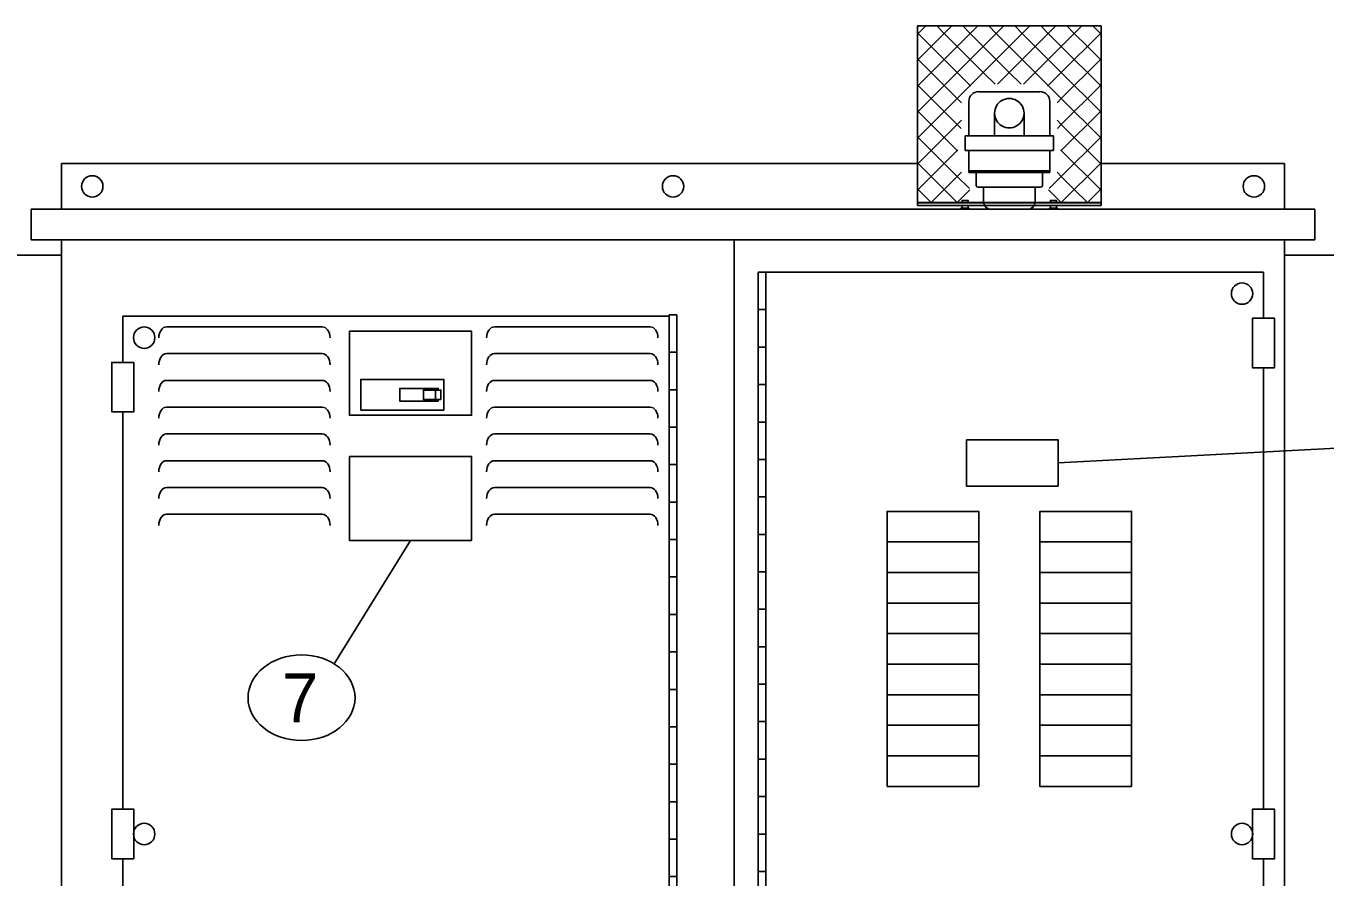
# Model space of a CAD drawing. Extents: x 99862 to 103680, y 99470 to 105076.
# Drawn here: x 100953.3 to 101378.5, y 100952 to 101230.5 of the extents above; entities that cross this region are included whole.
import ezdxf

# ---------------------------------------------------------------- set-up
doc = ezdxf.new("R2010")
doc.units = 0
for name, color, linetype in [('Level 1', 7, 'Continuous'), ('Level 11', 7, 'Continuous'), ('Level 15', 7, 'Continuous'), ('Level 20', 7, 'Continuous'), ('Level 34', 7, 'Continuous'), ('Level 40', 7, 'Continuous')]:
    doc.layers.add(name, color=color, linetype=linetype)

msp = doc.modelspace()

# ---------------------------------------------------------------- linework, layer by layer
at = {"layer": 'Level 1'}
for p, q in [((101244.91, 101172.75), (101244.91, 101230.51)), ((101304.91, 101230.51), (101244.91, 101230.51)), ((101244.91, 101228.28), (101245.13, 101228.06)), ((101245.13, 101228.06), (101247.58, 101230.51)), ((101251.19, 101230.51), (101253.64, 101228.06)), ((101256.09, 101230.51), (101253.64, 101228.06)), ((101262.15, 101228.06), (101259.7, 101230.51)), ((101264.6, 101230.51), (101262.15, 101228.06)), ((101270.66, 101228.06), (101268.2, 101230.51)), ((101273.11, 101230.51), (101270.66, 101228.06)), ((101279.16, 101228.06), (101276.71, 101230.51)), ((101281.62, 101230.51), (101279.16, 101228.06)), ((101287.67, 101228.06), (101285.22, 101230.51)), ((101290.12, 101230.51), (101287.67, 101228.06)), ((101293.73, 101230.51), (101296.18, 101228.06)), ((101296.18, 101228.06), (101298.63, 101230.51)), ((101304.69, 101228.06), (101302.24, 101230.51)), ((101304.91, 101228.28), (101304.69, 101228.06)), ((101304.91, 101172.75), (101304.91, 101230.51)), ((101245.13, 101228.06), (101244.91, 101227.84)), ((101249.38, 101223.8), (101245.13, 101228.06)), ((101253.64, 101228.06), (101249.38, 101223.8)), ((101253.64, 101228.06), (101257.89, 101223.8)), ((101257.89, 101223.8), (101262.15, 101228.06)), ((101262.15, 101228.06), (101266.4, 101223.8)), ((101266.4, 101223.8), (101270.66, 101228.06)), ((101270.66, 101228.06), (101274.91, 101223.8)), ((101274.91, 101223.8), (101279.16, 101228.06)), ((101279.16, 101228.06), (101283.42, 101223.8)), ((101283.42, 101223.8), (101287.67, 101228.06)), ((101287.67, 101228.06), (101291.93, 101223.8)), ((101291.93, 101223.8), (101296.18, 101228.06)), ((101296.18, 101228.06), (101300.44, 101223.8)), ((101300.44, 101223.8), (101304.69, 101228.06)), ((101304.69, 101228.06), (101304.91, 101227.84)), ((101244.91, 101219.77), (101245.13, 101219.55)), ((101245.13, 101219.55), (101249.38, 101223.8)), ((101249.38, 101223.8), (101253.64, 101219.55)), ((101257.89, 101223.8), (101253.64, 101219.55)), ((101262.15, 101219.55), (101257.89, 101223.8)), ((101266.4, 101223.8), (101262.15, 101219.55)), ((101270.66, 101219.55), (101266.4, 101223.8)), ((101274.91, 101223.8), (101270.66, 101219.55)), ((101279.16, 101219.55), (101274.91, 101223.8)), ((101283.42, 101223.8), (101279.16, 101219.55)), ((101287.67, 101219.55), (101283.42, 101223.8)), ((101291.93, 101223.8), (101287.67, 101219.55)), ((101296.18, 101219.55), (101291.93, 101223.8)), ((101300.44, 101223.8), (101296.18, 101219.55)), ((101304.69, 101219.55), (101300.44, 101223.8)), ((101304.91, 101219.77), (101304.69, 101219.55)), ((101245.13, 101219.55), (101244.91, 101219.33)), ((101249.38, 101215.3), (101245.13, 101219.55)), ((101253.64, 101219.55), (101249.38, 101215.3)), ((101253.64, 101219.55), (101257.89, 101215.3)), ((101257.89, 101215.3), (101262.15, 101219.55)), ((101262.15, 101219.55), (101266.4, 101215.3)), ((101266.4, 101215.3), (101270.66, 101219.55)), ((101270.66, 101219.55), (101274.91, 101215.3)), ((101274.91, 101215.3), (101279.16, 101219.55)), ((101279.16, 101219.55), (101283.42, 101215.3)), ((101283.42, 101215.3), (101287.67, 101219.55)), ((101287.67, 101219.55), (101291.93, 101215.3)), ((101291.93, 101215.3), (101296.18, 101219.55)), ((101296.18, 101219.55), (101300.44, 101215.3)), ((101300.44, 101215.3), (101304.69, 101219.55)), ((101304.69, 101219.55), (101304.91, 101219.33)), ((101244.91, 101211.26), (101245.13, 101211.04)), ((101245.13, 101211.04), (101249.38, 101215.3)), ((101249.38, 101215.3), (101253.64, 101211.04)), ((101257.89, 101215.3), (101253.64, 101211.04)), ((101262.15, 101211.04), (101257.89, 101215.3)), ((101266.4, 101215.3), (101262.15, 101211.04)), ((101270.28, 101211.42), (101266.4, 101215.3)), ((101274.91, 101215.3), (101271.04, 101211.42)), ((101278.78, 101211.42), (101274.91, 101215.3)), ((101283.42, 101215.3), (101279.54, 101211.42)), ((101287.67, 101211.04), (101283.42, 101215.3)), ((101291.93, 101215.3), (101287.67, 101211.04)), ((101296.18, 101211.04), (101291.93, 101215.3)), ((101300.44, 101215.3), (101296.18, 101211.04)), ((101304.69, 101211.04), (101300.44, 101215.3)), ((101304.91, 101211.26), (101304.69, 101211.04)), ((101245.13, 101211.04), (101244.91, 101210.82)), ((101249.38, 101206.79), (101245.13, 101211.04)), ((101253.64, 101211.04), (101249.38, 101206.79)), ((101253.64, 101211.04), (101257.89, 101206.79)), ((101257.89, 101206.79), (101262.15, 101211.04)), ((101262.15, 101211.04), (101262.36, 101210.83)), ((101284.94, 101209.01), (101264.88, 101209.01)), ((101287.46, 101210.82), (101287.67, 101211.04)), ((101287.67, 101211.04), (101291.93, 101206.79)), ((101291.93, 101206.79), (101296.18, 101211.04)), ((101296.18, 101211.04), (101300.44, 101206.79)), ((101300.44, 101206.79), (101304.69, 101211.04)), ((101304.69, 101211.04), (101304.91, 101210.82)), ((101244.91, 101202.75), (101245.13, 101202.53)), ((101245.13, 101202.53), (101249.38, 101206.79)), ((101249.38, 101206.79), (101253.64, 101202.53)), ((101257.89, 101206.79), (101253.64, 101202.53)), ((101259.27, 101205.41), (101257.89, 101206.79)), ((101261.67, 101194.58), (101261.67, 101205.81)), ((101288.15, 101194.58), (101288.15, 101205.81)), ((101291.93, 101206.79), (101290.55, 101205.41)), ((101296.18, 101202.53), (101291.93, 101206.79)), ((101300.44, 101206.79), (101296.18, 101202.53)), ((101304.69, 101202.53), (101300.44, 101206.79)), ((101304.91, 101202.75), (101304.69, 101202.53)), ((101245.13, 101202.53), (101244.91, 101202.31)), ((101249.38, 101198.28), (101245.13, 101202.53)), ((101253.64, 101202.53), (101249.38, 101198.28)), ((101253.64, 101202.53), (101257.89, 101198.28)), ((101257.89, 101198.28), (101259.27, 101199.65)), ((101270.1, 101194.58), (101270.1, 101201.96)), ((101279.72, 101194.58), (101279.72, 101201.96)), ((101290.55, 101199.65), (101291.93, 101198.28)), ((101291.93, 101198.28), (101296.18, 101202.53)), ((101296.18, 101202.53), (101300.44, 101198.28)), ((101300.44, 101198.28), (101304.69, 101202.53)), ((101304.69, 101202.53), (101304.91, 101202.31)), ((101244.91, 101194.25), (101245.13, 101194.02)), ((101245.13, 101194.02), (101249.38, 101198.28)), ((101249.38, 101198.28), (101253.64, 101194.02)), ((101257.89, 101198.28), (101253.64, 101194.02)), ((101259.19, 101196.98), (101257.89, 101198.28)), ((101261.67, 101194.58), (101260.47, 101194.58)), ((101260.47, 101194.58), (101260.47, 101189.76)), ((101261.67, 101194.58), (101288.15, 101194.58)), ((101288.15, 101194.58), (101289.35, 101194.58)), ((101289.35, 101194.58), (101289.35, 101189.76)), ((101291.93, 101198.28), (101290.63, 101196.98)), ((101296.18, 101194.02), (101291.93, 101198.28)), ((101300.44, 101198.28), (101296.18, 101194.02)), ((101304.69, 101194.02), (101300.44, 101198.28)), ((101304.91, 101194.25), (101304.69, 101194.02)), ((101245.13, 101194.02), (101244.91, 101193.8)), ((101249.38, 101189.77), (101245.13, 101194.02)), ((101253.64, 101194.02), (101249.38, 101189.77)), ((101253.64, 101194.02), (101257.89, 101189.77)), ((101291.93, 101189.77), (101296.18, 101194.02)), ((101296.18, 101194.02), (101300.44, 101189.77)), ((101300.44, 101189.77), (101304.69, 101194.02)), ((101304.69, 101194.02), (101304.91, 101193.8)), ((101244.91, 101185.74), (101245.13, 101185.52)), ((101245.13, 101185.52), (101249.38, 101189.77)), ((101249.38, 101189.77), (101253.64, 101185.52)), ((101257.89, 101189.77), (101253.64, 101185.52)), ((101257.89, 101189.77), (101258.06, 101189.94)), ((101258.06, 101189.6), (101257.89, 101189.77)), ((101289.35, 101189.76), (101260.47, 101189.76)), ((101261.67, 101189.76), (101261.67, 101182.54)), ((101288.15, 101189.76), (101288.15, 101182.54)), ((101291.76, 101189.94), (101291.93, 101189.77)), ((101291.93, 101189.77), (101291.76, 101189.6)), ((101296.18, 101185.52), (101291.93, 101189.77)), ((101300.44, 101189.77), (101296.18, 101185.52)), ((101304.69, 101185.52), (101300.44, 101189.77)), ((101304.91, 101185.74), (101304.69, 101185.52)), ((101245.13, 101185.52), (101244.91, 101185.3)), ((101249.38, 101181.26), (101245.13, 101185.52)), ((101253.64, 101185.52), (101249.38, 101181.26)), ((101253.64, 101185.52), (101257.89, 101181.26)), ((101257.89, 101181.26), (101259.27, 101182.64)), ((101261.67, 101183.14), (101288.15, 101183.14)), ((101261.67, 101182.54), (101288.15, 101182.54)), ((101264.08, 101178.33), (101264.08, 101182.54)), ((101285.74, 101178.33), (101285.74, 101182.54)), ((101290.55, 101182.64), (101291.93, 101181.26)), ((101291.93, 101181.26), (101296.18, 101185.52)), ((101296.18, 101185.52), (101300.44, 101181.26)), ((101300.44, 101181.26), (101304.69, 101185.52)), ((101304.69, 101185.52), (101304.91, 101185.3)), ((101244.91, 101177.23), (101245.13, 101177.01)), ((101245.13, 101177.01), (101249.38, 101181.26)), ((101249.38, 101181.26), (101253.64, 101177.01)), ((101257.89, 101181.26), (101253.64, 101177.01)), ((101261.86, 101177.3), (101257.89, 101181.26)), ((101264.68, 101177.73), (101285.14, 101177.73)), ((101266.49, 101172.92), (101266.49, 101177.73)), ((101283.33, 101172.92), (101283.33, 101177.73)), ((101291.93, 101181.26), (101287.96, 101177.3)), ((101296.18, 101177.01), (101291.93, 101181.26)), ((101300.44, 101181.26), (101296.18, 101177.01)), ((101304.69, 101177.01), (101300.44, 101181.26)), ((101304.91, 101177.23), (101304.69, 101177.01)), ((101245.13, 101177.01), (101244.91, 101176.79)), ((101249.38, 101172.75), (101245.13, 101177.01)), ((101253.64, 101177.01), (101249.38, 101172.75)), ((101253.64, 101177.01), (101257.89, 101172.75)), ((101257.89, 101172.75), (101262.04, 101176.9)), ((101287.78, 101176.9), (101291.93, 101172.75)), ((101291.93, 101172.75), (101296.18, 101177.01)), ((101296.18, 101177.01), (101300.44, 101172.75)), ((101300.44, 101172.75), (101304.69, 101177.01)), ((101304.69, 101177.01), (101304.91, 101176.79)), ((101304.91, 101172.75), (101244.91, 101172.75)), ((101244.91, 101171.71), (101244.91, 101172.65)), ((101304.91, 101172.65), (101244.91, 101172.65)), ((101304.91, 101171.71), (101244.91, 101171.71)), ((101268.89, 101170.51), (101280.93, 101170.51)), ((101304.91, 101171.71), (101304.91, 101172.65)), ((101087.23, 101111.36), (101087.23, 101108.3))]:
    msp.add_line(p, q, dxfattribs=at)
for points in [[(101354.44, 101134.84), (101361.68, 101134.84), (101361.68, 101118.69), (101354.44, 101118.69)], [(101059.03, 101130.61), (101099.03, 101130.61), (101099.03, 101103.11), (101059.03, 101103.11)], [(100988.53, 101120.41), (100981.29, 101120.41), (100981.29, 101104.26), (100988.53, 101104.26)], [(101062.78, 101104.83), (101089.97, 101104.83), (101089.97, 101114.83), (101062.78, 101114.83)], [(101088.99, 101108.3), (101083.23, 101108.3), (101083.23, 101111.36), (101088.99, 101111.36)], [(101234.91, 101061.66), (101264.91, 101061.66), (101264.91, 101071.66), (101234.91, 101071.66)], [(101284.91, 101061.66), (101314.91, 101061.66), (101314.91, 101071.66), (101284.91, 101071.66)], [(101234.91, 101051.66), (101264.91, 101051.66), (101264.91, 101061.66), (101234.91, 101061.66)], [(101284.91, 101051.66), (101314.91, 101051.66), (101314.91, 101061.66), (101284.91, 101061.66)], [(101234.91, 101041.66), (101264.91, 101041.66), (101264.91, 101051.66), (101234.91, 101051.66)], [(101284.91, 101041.66), (101314.91, 101041.66), (101314.91, 101051.66), (101284.91, 101051.66)], [(101234.91, 101031.66), (101264.91, 101031.66), (101264.91, 101041.66), (101234.91, 101041.66)], [(101284.91, 101031.66), (101314.91, 101031.66), (101314.91, 101041.66), (101284.91, 101041.66)], [(101234.91, 101021.66), (101264.91, 101021.66), (101264.91, 101031.66), (101234.91, 101031.66)], [(101284.91, 101021.66), (101314.91, 101021.66), (101314.91, 101031.66), (101284.91, 101031.66)], [(101234.91, 101011.66), (101264.91, 101011.66), (101264.91, 101021.66), (101234.91, 101021.66)], [(101284.91, 101011.66), (101314.91, 101011.66), (101314.91, 101021.66), (101284.91, 101021.66)], [(101234.91, 101001.66), (101264.91, 101001.66), (101264.91, 101011.66), (101234.91, 101011.66)], [(101284.91, 101001.66), (101314.91, 101001.66), (101314.91, 101011.66), (101284.91, 101011.66)], [(101234.91, 100991.66), (101264.91, 100991.66), (101264.91, 101001.66), (101234.91, 101001.66)], [(101284.91, 100991.66), (101314.91, 100991.66), (101314.91, 101001.66), (101284.91, 101001.66)], [(101234.91, 100981.66), (101264.91, 100981.66), (101264.91, 100991.66), (101234.91, 100991.66)], [(101284.91, 100981.66), (101314.91, 100981.66), (101314.91, 100991.66), (101284.91, 100991.66)], [(100988.53, 100958), (100981.29, 100958), (100981.29, 100974.15), (100988.53, 100974.15)], [(101354.44, 100958), (101361.68, 100958), (101361.68, 100974.15), (101354.44, 100974.15)]]:
    msp.add_lwpolyline(points, close=True, dxfattribs=at)
msp.add_lwpolyline([(101088.1, 101111.36), (101088.1, 101111.91), (101075.5, 101111.91), (101075.5, 101107.75), (101088.1, 101107.75), (101088.1, 101108.3)], dxfattribs=at)
for centre in [(101351.06, 101142.94), (100991.91, 101128.51), (100991.91, 100966.07), (101351.06, 100966.07)]:
    msp.add_circle(centre, 3.5, dxfattribs=at)
for centre, radius, start, end in [((101264.88, 101205.81), 3.21, 90, 180), ((101284.94, 101205.81), 3.21, 0, 90), ((101274.91, 101201.96), 4.81, 359.9997, 180), ((101274.91, 101201.96), 4.81, 180, 0.0003), ((101264.68, 101178.33), 0.602, 180, 270), ((101285.14, 101178.33), 0.602, 270, 0), ((101268.89, 101172.92), 2.41, 180, 270), ((101280.93, 101172.92), 2.41, 270, 0)]:
    msp.add_arc(centre, radius, start, end, dxfattribs=at)
at = {"layer": 'Level 11'}
for p, q in [((101050.15, 101132.06), (100999.24, 101132.06)), ((101157.41, 101132.06), (101106.5, 101132.06)), ((101050.15, 101123.3), (100999.24, 101123.3)), ((101157.41, 101123.3), (101106.5, 101123.3)), ((101050.15, 101114.54), (100999.24, 101114.54)), ((101157.41, 101114.54), (101106.5, 101114.54)), ((101050.15, 101105.77), (100999.24, 101105.77)), ((101157.41, 101105.77), (101106.5, 101105.77)), ((101050.15, 101097.01), (100999.24, 101097.01)), ((101157.41, 101097.01), (101106.5, 101097.01)), ((101050.15, 101088.25), (100999.24, 101088.25)), ((101157.41, 101088.25), (101106.5, 101088.25)), ((101050.15, 101079.48), (100999.24, 101079.48)), ((101157.41, 101079.48), (101106.5, 101079.48)), ((101050.15, 101070.72), (100999.24, 101070.72)), ((101157.41, 101070.72), (101106.5, 101070.72))]:
    msp.add_line(p, q, dxfattribs=at)
for centre, start_param, end_param in [((100999.24, 101128.43), 0, 1.570796), ((101050.15, 101128.43), 4.712389, 6.283185), ((101106.5, 101128.43), 0, 1.570796), ((101157.41, 101128.43), 4.712389, 6.283185), ((100999.24, 101119.66), 0, 1.570796), ((101050.15, 101119.66), 4.712389, 6.283185), ((101106.5, 101119.66), 0, 1.570796), ((101157.41, 101119.66), 4.712389, 6.283185), ((100999.24, 101110.9), 0, 1.570796), ((101050.15, 101110.9), 4.712389, 6.283185), ((101106.5, 101110.9), 0, 1.570796), ((101157.41, 101110.9), 4.712389, 6.283185), ((100999.24, 101102.14), 0, 1.570796), ((101050.15, 101102.14), 4.712389, 6.283185), ((101106.5, 101102.14), 0, 1.570796), ((101157.41, 101102.14), 4.712389, 6.283185), ((100999.24, 101093.37), 0, 1.570796), ((101050.15, 101093.37), 4.712389, 6.283185), ((101106.5, 101093.37), 0, 1.570796), ((101157.41, 101093.37), 4.712389, 6.283185), ((100999.24, 101084.61), 0, 1.570796), ((101050.15, 101084.61), 4.712389, 6.283185), ((101106.5, 101084.61), 0, 1.570796), ((101157.41, 101084.61), 4.712389, 6.283185), ((100999.24, 101075.84), 0, 1.570796), ((101050.15, 101075.84), 4.712389, 6.283185), ((101106.5, 101075.84), 0, 1.570796), ((101157.41, 101075.84), 4.712389, 6.283185), ((100999.24, 101067.08), 0, 1.570796), ((101050.15, 101067.08), 4.712389, 6.283185), ((101106.5, 101067.08), 0, 1.570796), ((101157.41, 101067.08), 4.712389, 6.283185)]:
    msp.add_ellipse(centre, major_axis=(0, 3.64), ratio=0.707107, start_param=start_param, end_param=end_param, dxfattribs=at)
at = {"layer": 'Level 15'}
for p, q in [((100954.91, 101170.51), (101374.91, 101170.51)), ((100954.91, 101160.51), (100954.91, 101170.51)), ((101374.91, 101170.51), (101374.91, 101160.51)), ((100954.91, 101160.51), (101374.91, 101160.51)), ((101394.77, 101093.03), (101290.89, 101087.52)), ((101079.03, 101062.15), (101054.09, 101021.75))]:
    msp.add_line(p, q, dxfattribs=at)
for centre in [(100974.91, 101178.01), (101164.91, 101178.01), (101354.91, 101178.01)]:
    msp.add_circle(centre, 3.5, dxfattribs=at)
at = {"layer": 'Level 20'}
msp.add_ellipse((101043.39, 101010.67), major_axis=(-17.5, 0), ratio=0.8, dxfattribs=at)
at = {"layer": 'Level 34'}
for points in [[(101260.89, 101095.12), (101290.89, 101095.12), (101290.89, 101079.92), (101260.89, 101079.92)], [(101059.03, 101089.65), (101099.03, 101089.65), (101099.03, 101062.15), (101059.03, 101062.15)]]:
    msp.add_lwpolyline(points, close=True, dxfattribs=at)
at = {"layer": 'Level 40'}
for p, q in [((100964.91, 101185.51), (101244.91, 101185.51)), ((100964.91, 101170.51), (100964.91, 101185.51)), ((101304.91, 101185.51), (101364.91, 101185.51)), ((101364.91, 101170.51), (101364.91, 101185.51)), ((100964.91, 101170.51), (101364.91, 101170.51)), ((100964.91, 100755.51), (100964.91, 101160.51)), ((101184.91, 100770.51), (101184.91, 101160.51)), ((101364.91, 101160.51), (101364.91, 100755.51)), ((100964.91, 101155.51), (100744.91, 101155.51)), ((101364.91, 101155.51), (101544.91, 101155.51)), ((101192.75, 100782.2), (101192.75, 101149.94)), ((101192.75, 101149.94), (101195.23, 101149.94)), ((101195.23, 100782.2), (101195.23, 101149.94)), ((101195.23, 101149.94), (101358.06, 101149.94)), ((101358.06, 101149.94), (101358.06, 101134.84)), ((100984.91, 101135.51), (101163.67, 101135.51)), ((100984.91, 101120.41), (100984.91, 101135.51)), ((101163.67, 100805.03), (101163.67, 101135.99)), ((101163.67, 101135.99), (101166.15, 101135.99)), ((101166.15, 100805.03), (101166.15, 101135.99)), ((101192.75, 101137.68), (101195.23, 101137.68)), ((101163.67, 101123.74), (101166.15, 101123.74)), ((101192.75, 101125.43), (101195.23, 101125.43)), ((101358.06, 101118.69), (101358.06, 100974.15)), ((101163.67, 101111.48), (101166.15, 101111.48)), ((101192.75, 101113.17), (101195.23, 101113.17)), ((100984.91, 100974.15), (100984.91, 101104.26)), ((101192.75, 101100.91), (101195.23, 101100.91)), ((101163.67, 101099.22), (101166.15, 101099.22)), ((101192.75, 101088.65), (101195.23, 101088.65)), ((101163.67, 101086.96), (101166.15, 101086.96)), ((101192.75, 101076.39), (101195.23, 101076.39)), ((101163.67, 101074.7), (101166.15, 101074.7)), ((101163.67, 101062.45), (101166.15, 101062.45)), ((101192.75, 101064.14), (101195.23, 101064.14)), ((101163.67, 101050.19), (101166.15, 101050.19)), ((101192.75, 101051.88), (101195.23, 101051.88)), ((101163.67, 101037.93), (101166.15, 101037.93)), ((101192.75, 101039.62), (101195.23, 101039.62)), ((101163.67, 101025.67), (101166.15, 101025.67)), ((101192.75, 101027.36), (101195.23, 101027.36)), ((101163.67, 101013.41), (101166.15, 101013.41)), ((101192.75, 101015.1), (101195.23, 101015.1)), ((101163.67, 101001.16), (101166.15, 101001.16)), ((101192.75, 101002.85), (101195.23, 101002.85)), ((101192.75, 100990.59), (101195.23, 100990.59)), ((101163.67, 100988.9), (101166.15, 100988.9)), ((101192.75, 100978.33), (101195.23, 100978.33)), ((101163.67, 100976.64), (101166.15, 100976.64)), ((101192.75, 100966.07), (101195.23, 100966.07)), ((101163.67, 100964.38), (101166.15, 100964.38)), ((100984.91, 100836.77), (100984.91, 100958)), ((101358.06, 100958), (101358.06, 100813.46)), ((101163.67, 100952.12), (101166.15, 100952.12)), ((101192.75, 100953.81), (101195.23, 100953.81))]:
    msp.add_line(p, q, dxfattribs=at)
for points in [[(101261.45, 101172.68), (101261.45, 101173.45), (101259.49, 101173.45), (101259.49, 101172.68)], [(101288.36, 101172.68), (101288.36, 101173.45), (101290.33, 101173.45), (101290.33, 101172.68)], [(101261.81, 101170.75), (101261.81, 101170.51), (101259.13, 101170.51), (101259.13, 101170.75)], [(101261.79, 101170.92), (101261.79, 101170.75), (101259.16, 101170.75), (101259.16, 101170.92)], [(101261.45, 101170.92), (101261.45, 101171.71), (101259.49, 101171.71), (101259.49, 101170.92)], [(101288, 101170.75), (101288, 101170.51), (101290.69, 101170.51), (101290.69, 101170.75)], [(101288.03, 101170.92), (101288.03, 101170.75), (101290.66, 101170.75), (101290.66, 101170.92)], [(101288.36, 101170.92), (101288.36, 101171.71), (101290.33, 101171.71), (101290.33, 101170.92)]]:
    msp.add_lwpolyline(points, close=True, dxfattribs=at)

# ---------------------------------------------------------------- texts
at = {"layer": 'Level 20'}
msp.add_text('7', height=16, dxfattribs=at).set_placement((101036.96, 101002.67))

doc.saveas('drawing.dxf')
